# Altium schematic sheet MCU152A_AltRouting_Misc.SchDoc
size 431 x 279 mm; Date: Not shown in title block; ApprovedBy: Not shown in title block; CheckedBy: Not shown in title block; Author: Not shown in title block; CompanyName: Not shown in title block; Engineer: Not shown in title block; Organization: Not shown in title block; Address1: Not shown in title block; Address2: Not shown in title block; Address3: Not shown in title block; Address4: Not shown in title block; DocumentNumber: 3; Revision: Use project parameter SCH_Rev; SheetNumber: 3; SheetTotal: 8; PageSetup: Record=PageOptions¦CenterHorizontal=True¦CenterVertical=True¦PrintScale=1.00¦XCorrection=1.00¦YCorrection=1.00¦PrintKind=0¦BorderSize=5000000¦LeftOffset=0¦BottomOffset=0¦Orientation=2¦PaperLength=1000¦PaperWidth=1000¦Scale=100¦PaperSource=15¦PrintQuality=600¦MediaType=1¦DitherType=10¦PaperKind=Letter¦PrintScaleMode=1
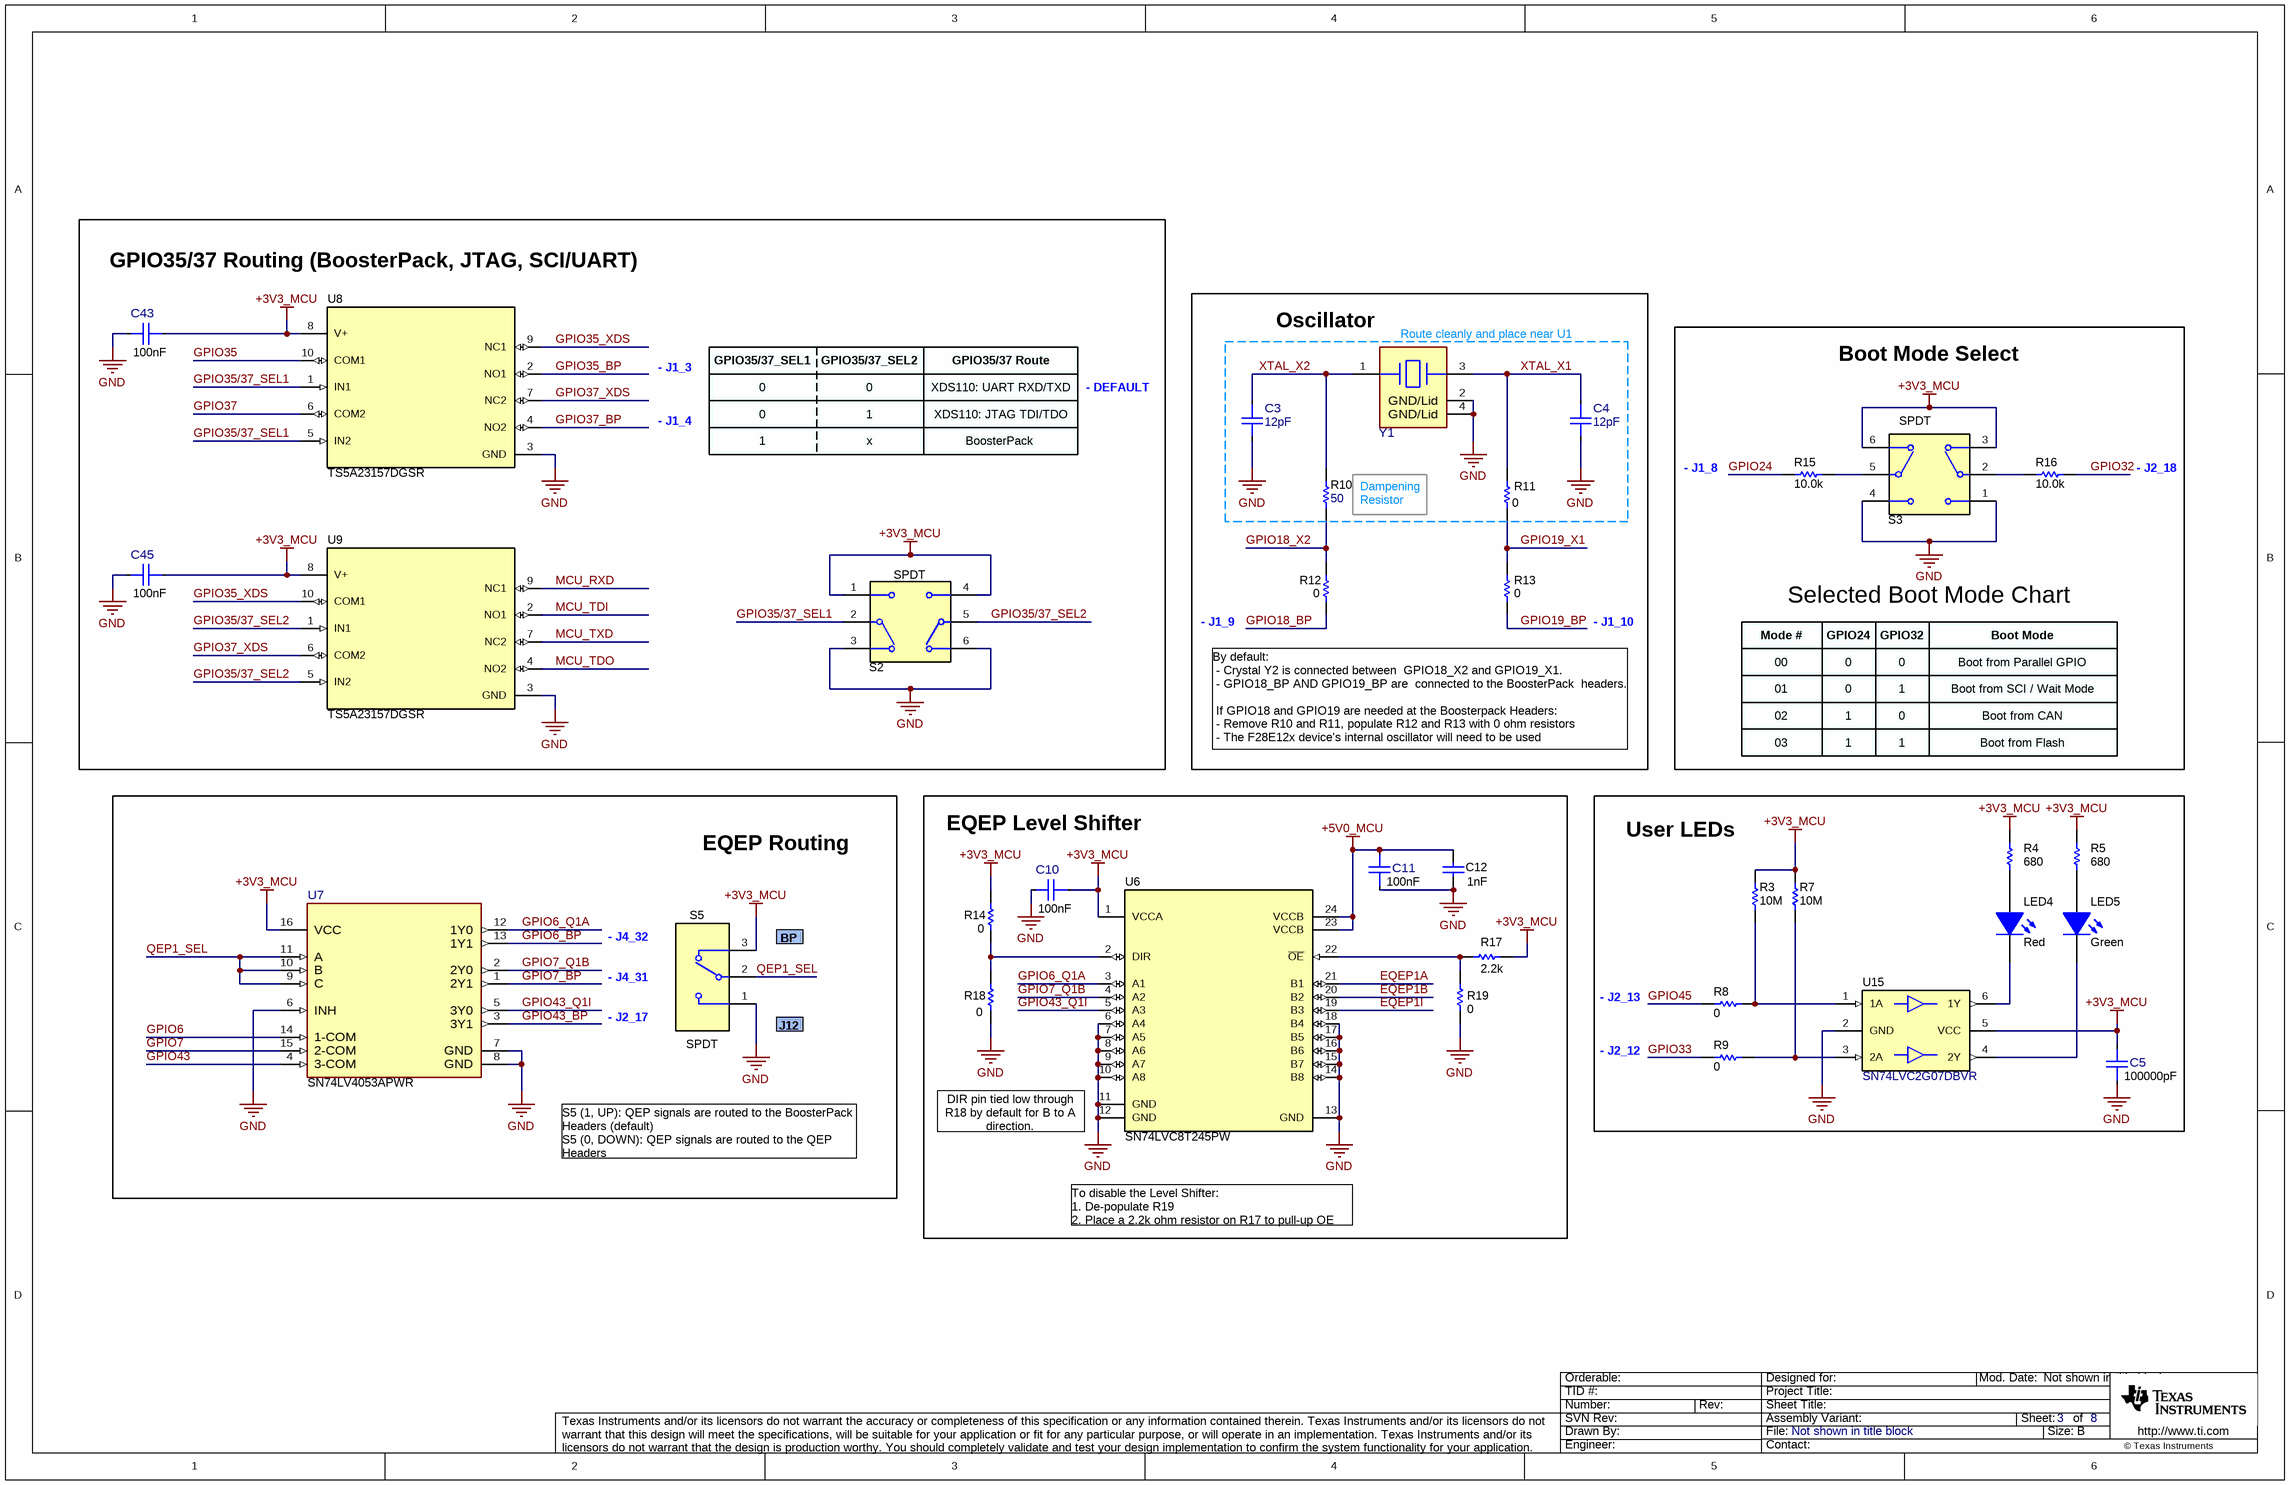
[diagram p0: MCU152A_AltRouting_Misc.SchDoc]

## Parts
C3  ValueDisplayed: 12pF  [FP-885392005127_0402-MFG]  (hidden comment: 885392005127)
C4  ValueDisplayed: 12pF  [FP-885392005127_0402-MFG]  (hidden comment: 885392005127)
C5  ValueDisplayed: 100000pF  [FP-885012205018_0402-MFG]  (hidden comment: 885012205018)
C10  Cap_F: 100nF  [FP-885012205018_0402-MFG]  (hidden comment: 885012205018)
C11  Cap_F: 100nF  [FP-885012205018_0402-MFG]  (hidden comment: 885012205018)
C12  Cap_F: 1nF  [0402]  (hidden comment: 885012205061)
C43  Cap_F: 100nF  [FP-885012205018_0402-MFG]  (hidden comment: 885012205018)
C45  Cap_F: 100nF  [FP-885012205018_0402-MFG]  (hidden comment: 885012205018)
LED4  value Red  [WL-SMCW_RED_0805]  (hidden comment: 150080SS75000)
LED5  value Green  [WL-SMCW_Green_0805]  (hidden comment: 150080GS75000)
R3  ValueDisplayed: 10M  [0402]  (hidden comment: CRCW040210M0JNED)
R4  ValueDisplayed: 680  [0402]  (hidden comment: CRCW0402680RJNED)
R5  ValueDisplayed: 680  [0402]  (hidden comment: CRCW0402680RJNED)
R7  ValueDisplayed: 10M  [0402]  (hidden comment: CRCW040210M0JNED)
R8  ValueDisplayed: 0  [0603]  (hidden comment: CRCW06030000Z0EA)
R9  ValueDisplayed: 0  [0603]  (hidden comment: CRCW06030000Z0EA)
R10  ValueDisplayed: 50  [0603]  (hidden comment: FC0603E50R0BTBST1)
R11  ValueDisplayed: 0  [0603]  (hidden comment: CRCW06030000Z0EA)
R12  ValueDisplayed: 0  [0603]  (hidden comment: CRCW06030000Z0EA)
R13  ValueDisplayed: 0  [0603]  (hidden comment: CRCW06030000Z0EA)
R14  ValueDisplayed: 0  [0603]  (hidden comment: CRCW06030000Z0EA)
R15  ValueDisplayed: 10.0k  [0603]  (hidden comment: RC0603FR-0710KL)
R16  ValueDisplayed: 10.0k  [0603]  (hidden comment: RC0603FR-0710KL)
R17  ValueDisplayed: 2.2k  [0603]  (hidden comment: CRCW06032K20JNEA)
R18  ValueDisplayed: 0  [0603]  (hidden comment: CRCW06030000Z0EA)
R19  ValueDisplayed: 0  [0603]  (hidden comment: CRCW06030000Z0EA)
S2  CAS-D20TA  [SW_CAS-D20TA]  (value not drawn)
S3  CAS-D20TA  [SW_CAS-D20TA]  (value not drawn)
S5  CAS-120TA  [SW_CAS-120TA]  (value not drawn)
U6  SN74LVC8T245PW  [PW0024A_N]
U7  SN74LV4053APWR  [PW0016A-MFG]
U8  TS5A23157DGSR  [DGS0010A_N]
U9  TS5A23157DGSR  [DGS0010A_N]
U15  SN74LVC2G07DBVR  [DBV0006A_N]
Y1  830108207209  [FP-830108207209_SMT_CRYSTAL_3MM2_2MM5-MFG]  (value not drawn)

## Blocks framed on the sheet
GPIO35/37 Routing (BoosterPack, JTAG, SCI/UART): C43 C45 S2 U8 U9
Oscillator: C3 C4 R10-R13 Y1
Selected Boot Mode Chart: R15 R16 S3
EQEP Routing: S5 U7
EQEP Level Shifter: C10-C12 R14 R17-R19 U6
User LEDs: C5 LED4 LED5 R3-R5 R7-R9 U15

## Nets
+3V3_MCU: C5.2 C10.1 C43.1 C45.1 R3.2 R4.2 R5.2 R7.2 R14.2 R17.2 S2.1 S2.4 S3.3 S3.6 S5.3 U6.1(VCCA) U7.16(VCC) U8.8(V+) U9.8(V+) U15.5(VCC)
+5V0_MCU: C11.2 C12.1 U6.23(VCCB) U6.24(VCCB)
GND: C3.2 C4.2 C5.1 C10.2 C11.1 C12.2 C43.2 C45.2 R18.1 R19.2 S2.3 S2.6 S3.1 S3.4 S5.1 U6.6(A4) U6.7(A5) U6.8(A6) U6.9(A7) U6.10(A8) U6.11(GND) U6.12(GND) U6.13(GND) U6.14(B8) U6.15(B7) U6.16(B6) U6.17(B5) U6.18(B4) U7.6(INH) U7.7(GND) U7.8(GND) U8.3(GND) U9.3(GND) U15.2(GND) Y1.2(GND/Lid) Y1.4(GND/Lid)
EQEP1A: U6.21(B1)
EQEP1B: U6.20(B2)
EQEP1I: U6.19(B3)
GPIO6: U7.14(1-COM)
GPIO6_BP: U7.13(1Y1)
GPIO6_Q1A: U6.3(A1) U7.12(1Y0)
GPIO7: U7.15(2-COM)
GPIO7_BP: U7.1(2Y1)
GPIO7_Q1B: U6.4(A2) U7.2(2Y0)
GPIO18_BP: R12.1
GPIO18_X2: R10.1 R12.2
GPIO19_BP: R13.1
GPIO19_X1: R11.1 R13.2
GPIO24: R15.1
GPIO32: R16.2
GPIO33: R9.1
GPIO35: U8.10(COM1)
GPIO35/37_SEL1: S2.2(C) U8.1(IN1) U8.5(IN2)
GPIO35/37_SEL2: S2.5(C) U9.1(IN1) U9.5(IN2)
GPIO35_BP: U8.2(NO1)
GPIO35_XDS: U8.9(NC1) U9.10(COM1)
GPIO37: U8.6(COM2)
GPIO37_BP: U8.4(NO2)
GPIO37_XDS: U8.7(NC2) U9.6(COM2)
GPIO43: U7.4(3-COM)
GPIO43_BP: U7.3(3Y1)
GPIO43_Q1I: U6.5(A3) U7.5(3Y0)
GPIO45: R8.1
MCU_RXD: U9.9(NC1)
MCU_TDI: U9.2(NO1)
MCU_TDO: U9.4(NO2)
MCU_TXD: U9.7(NC2)
QEP1_SEL: S5.2 U7.9(C) U7.10(B) U7.11(A)
XTAL_X1: C4.1 R11.2 Y1.3(2_Crystal)
XTAL_X2: C3.1 R10.2 Y1.1(1_Crystal)
NetLED4_1: LED4.1(K) U15.6(1Y)
NetLED4_2: LED4.2(A) R4.1
NetLED5_1: LED5.1(K) U15.4(2Y)
NetLED5_2: LED5.2(A) R5.1
NetR3_1: R3.1 R8.2 U15.1(1A)
NetR7_1: R7.1 R9.2 U15.3(2A)
NetR14_1: R14.1 R18.2 U6.2(DIR)
NetR15_2: R15.2 S3.5(C)
NetR16_1: R16.1 S3.2(C)
NetR17_1: R17.1 R19.1 U6.22(~{OE})

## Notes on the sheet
- - J1_3
- GPIO35/37_SEL1
- GPIO35/37_SEL2
- GPIO35/37 Route
- (near Y1) Route cleanly and place near U1
- Boot Mode Select
- - J1_4
- 0
- 1
- x
- BoosterPack
- XDS110: UART RXD/TXD
- XDS110: JTAG TDI/TDO
- - DEFAULT
- (near S3) SPDT
- (near R10) Dampening
- - J1_8
- - J2_18
- (near S2) SPDT
- (near R10) Resistor
- - J1_9
- - J1_10
- Mode #
- GPIO24
- GPIO32
- Boot Mode
- 00
- 01
- Boot from Parallel GPIO
- Boot from SCI / Wait Mode
- By default:
  - Crystal Y2 is connected between  GPIO18_X2 and GPIO19_X1.
  - GPIO18_BP AND GPIO19_BP are  connected to the BoosterPack  headers.
  If GPIO18 and GPIO19 are needed at the Boosterpack Headers:
  - Remove R10 and R11, populate R12 and R13 with 0 ohm resistors
  - The F28E12x device's internal oscillator will need to be used
- 02
- 03
- Boot from CAN
- Boot from Flash
- - J4_32
- - J4_31
- (near S5) BP
- - J2_17
- (near S5) J12
- - J2_13
- (near S5) SPDT
- - J2_12
- S5 (1, UP): QEP signals are routed to the BoosterPack Headers (default)
  S5 (0, DOWN): QEP signals are routed to the QEP Headers
- (near U6) DIR pin tied low through R18 by default for B to A direction.
- To disable the Level Shifter:
  1. De-populate R19
  2. Place a 2.2k ohm resistor on R17 to pull-up OE

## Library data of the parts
C3 C4 = CMP-0124909-1: 12 pF ±2% 50V Ceramic Capacitor C0G, NP0 0402 (1005 Metric); Manufacturer: Wurth; AEC Qualified: No; SizeZ_mm: 0.55mm; TempCo: 30ppm/°C; Value: 12pF
C5 = CMP-0090362-1: 0.1µF ±10% 10V Ceramic Capacitor X7R 0402 (1005 Metric); Manufacturer: Wurth Electronics; AEC Qualified: No; Value: 100nF; SizeZ_mm: 0.55mm; TempCo: 15%
C10 C11 C43 C45 = CMP-0090362-1: 0.1µF ±10% 10V Ceramic Capacitor X7R 0402 (1005 Metric); Manufacturer: Wurth Electronics; AEC Qualified: No; Value: 100nF; SizeZ_mm: 0.55mm; ValueDisplayed: 100000pF; TempCo: 15%
C12 = CMP-0006231-2: CAP, CERM, 1000 pF, 50 V, +/- 10%, X7R, 0402; Manufacturer: Wurth Elektronik; Polarized: N; Value: 1000pF; U/M: EA; Value1: Unknown; VDC_V: 50V; TaMin_C: -55°C; TaMax_C: 125°C; SizeArea_mm2: 0.5; SizeAreaWB_mm2: 3; SizeX_mm: 1; SizeZ_mm: 0.6; AEC Category: Q200
LED4 = CMP-0002951-3: LED, Red, SMD; Manufacturer: Wurth Elektronik; Type: AlInGaP; Vf_V: 1.9V; Io_A: 30mA; Vr_V: 5V; Ir_A: 25µA; Tjmax_C: 85°C; Power_TotalModule: 72mW; Value1: 0.072W; Angle: 140
LED5 = CMP-0003014-3: LED, Green, SMD; Manufacturer: Wurth Elektronik; Io_A: 20mA; Ir_A: 10µA; Angle: 140; Power_TotalModule: 105mW; Type: InGaN; Vf_V: 3.2V; Tjmax_C: 85°C; Value1: 0.105W; Vr_V: 5V
R3 R7 = CMP-0026826-2: RES, 10 M, 5%, 0.063 W, AEC-Q200 Grade 0, 0402; Manufacturer: Vishay-Dale; Value: 10Meg; Value_Code: 10M0; Power_W: 63mW; Value2: 0.063W; VDC_V: 50V; TempCo: 200 ppm/C; SizeArea_mm2: 0.5; SizeX_mm: 1; SizeZ_mm: 0.6; EIA_Code: E24; AEC Category: Q200; AEC Qualified: Y; AEC Grade: 0
R4 R5 = CMP-0026962-3: RES, 680, 5%, 0.063 W, AEC-Q200 Grade 0, 0402; Manufacturer: Vishay-Dale; Power_W: 63mW; TempCo: 200 ppm/C; Value_Code: 680R; Value: 680; EIA_Code: E24; SizeX_mm: 1; SizeY_mm: 0.5; SizeZ_mm: 0.6; Value2: 0.063W; AEC Qualified: Y; VDC_V: 50V; AEC Category: Q200; AEC Grade: 0
R8 R9 R11-R14 R18 R19 = CMP-0025697-4: RES, 0, 5%, 0.1 W, AEC-Q200 Grade 0, 0603; Manufacturer: Vishay-Dale; Value: 0; Value_Code: 0000; Power_W: 100mW; Value2: 0.1W; VDC_V: 75V; TempCo: 200 ppm/C; SizeArea_mm2: 1.28; SizeX_mm: 1.6; SizeY_mm: 0.8; SizeZ_mm: 1; EIA_Code: E24; AEC Category: Q200; AEC Qualified: Y
R10 = CMP-0023387-3: RES, 50, 0.1%, 0.125 W, 0603; Manufacturer: Vishay Thin Film; Power_W: 125mW; TempCo: 25 ppm/C; Value_Code: 50R0; U/M: EA; Value: 50; SizeX_mm: 1.6; SizeY_mm: 0.8; SizeZ_mm: 1; Value2: 0.125W; SizeArea_mm2: 1.28; AEC Qualified: N; VDC_V: 50V; AEC Category: Q200
R15 R16 = CMP-0022746-5: RES, 10.0 k, 1%, 0.1 W, 0603; Manufacturer: Yageo; Power_W: 100mW; TempCo: 100 ppm/C; Value_Code: 10k0; Value: 10.0k; EIA_Code: E96; Res_ohm: 10k; SizeX_mm: 1.6; SizeY_mm: 0.8; SizeZ_mm: 1; Value2: 0.1W; SizeArea_mm2: 1.28; AEC Qualified: N; VDC_V: 75V; AEC Category: Q200; SizeAreaWB_mm2: 4.68
R17 = CMP-0025769-4: RES, 2.2 k, 5%, 0.1 W, AEC-Q200 Grade 0, 0603; Manufacturer: Vishay-Dale; Value: 2.2k; Value_Code: 2k20; Power_W: 100mW; Value2: 0.1W; VDC_V: 75V; TempCo: 200 ppm/C; SizeArea_mm2: 1.28; SizeX_mm: 1.6; SizeY_mm: 0.8; SizeZ_mm: 1; EIA_Code: E24; AEC Category: Q200; AEC Qualified: Y; AEC Grade: 0
S2 = CMP-0002233-1: Switch, Dual SPDT,  2 Pos, 0.1A, 6VDC, SMD; Manufacturer: Copal Electronics; VDC_V: 6V; SwitchFunction: On-On; PositionCount: 2; CurrentRating_mA: 100A
S3 = CMP-0002233-1: Switch, Dual SPDT,  2 Pos, 0.1A, 6VDC, SMD; Manufacturer: Copal Electronics; CurrentRating_mA: 100A; SwitchFunction: On-On; VDC_V: 6V; PositionCount: 2
S5 = CMP-0002139-2: Switch, Slide, SPDT  100mA, SMT; Manufacturer: Copal Electronics; CurrentRating_mA: 100A; SwitchFunction: On-On; VDC_V: 6V; PositionCount: 1
U6 = CMP-0066458-2: 8-Bit Dual-Supply Bus Transceiver with Configurable Voltage-Level Shifting and Three-State Outputs, PW0024A (TSSOP-24); Alternate Manufacturer: Texas Instruments; SizeAreaWB_mm2: 82.32; SizeZ_mm: 1.2; SizeX_mm: 6.4; SizeY_mm: 7.8; SizeArea_mm2: 49.92; CompType: IC; AEC Category: Q200; AEC Qualified: N; Rating: Catalog
U7 = CMP-0089841-1: 3 Circuit IC Switch 2:1 75Ohm 16-TSSOP; Manufacturer: Texas Instruments; TaMax_C: +85°C; Max Supply Voltage: 5.5V; PositionCount: 3; AEC Qualified: No; SizeZ_mm: 1.2mm; Standoff Height: 0.05mm; On State Resistance: 100-225Ω; Min Supply Voltage: 2V; -3Db Bandwith: 50MHz; Nominal Supply Current: 20uA; TaMin_C: -40°C
U8 U9 = CMP-0067418-1: DUAL 10-Ohm SPDT ANALOG SWITCH, DGS0010A (VSSOP-10); Alternate PartNumber: TS5A23157DGST; Alternate Manufacturer: Texas Instruments; Green_Lifecycle: Active; SizeAreaWB_mm2: 23.6; Green_REACh: Passed; U/M: EA; SizeZ_mm: 1.1; SizeX_mm: 4.9; SizeY_mm: 3.0; SizeArea_mm2: 14.7; CompType: IC
U15 = CMP-0051789-2: Dual Buffer/Driver with Open-Drain Output, DBV0006A, LARGE T&R; Manufacturer: Texas Instruments; VCC(Min)(V): 1.65; VCC(Max)(V): 5.5; Output Type: CMOS; ICC @ Nom Voltage(Max)(mA): 0.01; Input Type: CMOS/TTL; Bits(#): 2; F @ Nom Voltage(Max)(Mhz): 150; Rating: Catalog; Technology Family: LVC; Voltage(Nom)(V): 1.8,2.5,3.3,5; Schmitt Trigger: No; Output Drive (IOL/IOH)(Max)(mA): 32/-32; tpd @ Nom Voltage(Max)(ns): 8.6,4.4,3.7,2.9; Logic: True; Sub-Family: Inverting Buffer/Driver; AEC Category: Q200; AEC Qualified: N; CompType: IC; Green_Lifecycle: Active; Green_REACh: Passed; SizeArea_mm2: 8.12; SizeAreaWB_mm2: 14.82; SizeX_mm: 2.8; SizeY_mm: 2.9; SizeZ_mm: 1.45
Y1 = CMP-0093781-1: 20 MHz ±10ppm Crystal 8pF 50 Ohms 4-SMD, No Lead; Manufacturer: Wurth Electronics; SizeZ_mm: 0.8mm; Frequency Stability: 20ppm; Esr: 50; Frequency_Fixed: 20MHz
